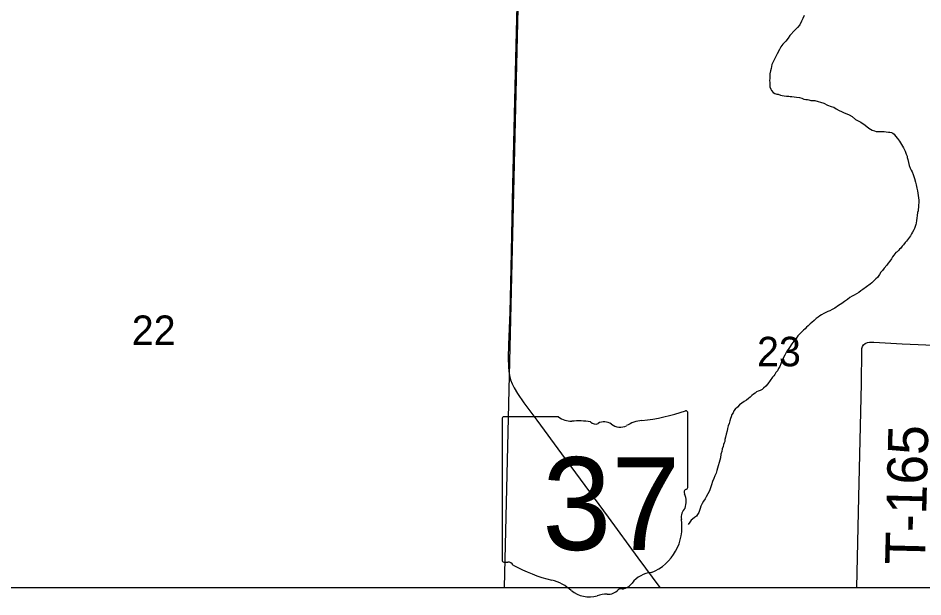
# Model space of a CAD drawing. Extents: x 0 to 68, y 0 to 52.9.
# Drawn here: x 47.275 to 48.632, y 31.129 to 31.998 of the extents above; entities that cross this region are included whole.
import ezdxf

# ---------------------------------------------------------------- set-up
doc = ezdxf.new("R2010")
doc.units = 0
for name, color, linetype in [('Default', 7, 'Continuous'), ('GM_X_Minor_River', 7, 'Continuous'), ('GM_X_State_Route', 7, 'Continuous'), ('GM_X_State_Shield', 7, 'Continuous'), ('GM_X_Township_Road', 7, 'Continuous'), ('GM_X_Township_Road_Text', 7, 'Continuous')]:
    doc.layers.add(name, color=color, linetype=linetype)

msp = doc.modelspace()

# ---------------------------------------------------------------- linework, layer by layer
at = {"layer": 'Default'}
msp.add_line((42.2581, 31.1431), (49.6501, 31.1431), dxfattribs=at)
msp.add_lwpolyline([(46.938, 31.1431), (46.9572, 32.0794), (48.0259, 32.0553), (48.0041, 31.1431)], dxfattribs=at)
at = {"layer": 'GM_X_Minor_River'}
for points in [[(48.4542, 32.0018), (48.4522, 31.9974), (48.4502, 31.9934), (48.4478, 31.9878), (48.4441, 31.9838), (48.4421, 31.9818), (48.4405, 31.9798), (48.4329, 31.9718), (48.4301, 31.9678), (48.4268, 31.9634), (48.4224, 31.9586), (48.4192, 31.9546), (48.4172, 31.9509), (48.414, 31.9441), (48.4115, 31.9393), (48.4095, 31.9353), (48.4075, 31.9313), (48.4059, 31.9281), (48.4051, 31.9253), (48.4047, 31.9221), (48.4039, 31.9185), (48.403, 31.9141), (48.4026, 31.9105), (48.4026, 31.9073), (48.4022, 31.904), (48.4026, 31.9012), (48.4026, 31.8988), (48.403, 31.8944), (48.4042, 31.8912), (48.4054, 31.8892), (48.4078, 31.886), (48.4102, 31.8844), (48.4134, 31.8835), (48.4154, 31.8835), (48.419, 31.8823), (48.4214, 31.8815), (48.4242, 31.8811), (48.4278, 31.8807), (48.4311, 31.8807), (48.4335, 31.8803), (48.4359, 31.8799), (48.4391, 31.8794), (48.4427, 31.879), (48.4471, 31.8786), (48.4507, 31.8774), (48.4539, 31.8762), (48.4567, 31.8758), (48.4591, 31.8754), (48.4611, 31.875), (48.4644, 31.8741), (48.4676, 31.8741), (48.4704, 31.8741), (48.4836, 31.8701), (48.4892, 31.8672), (48.4948, 31.8652), (48.4988, 31.864), (48.5025, 31.8616), (48.5069, 31.8592), (48.5105, 31.8575), (48.5141, 31.8555), (48.5181, 31.8543), (48.5217, 31.8527), (48.5261, 31.8499)], [(48.5261, 31.8499), (48.5313, 31.8458), (48.5393, 31.8414), (48.5457, 31.837), (48.5514, 31.8325), (48.5562, 31.8297), (48.5598, 31.8285), (48.5622, 31.8277), (48.5646, 31.8277), (48.5678, 31.8277), (48.571, 31.8277), (48.5742, 31.8276), (48.5774, 31.8272), (48.5806, 31.8268), (48.583, 31.8264), (48.5851, 31.826), (48.5871, 31.8252), (48.5891, 31.8236), (48.5915, 31.8208), (48.5943, 31.8171), (48.5975, 31.8131), (48.6003, 31.8083), (48.6031, 31.8031), (48.6059, 31.7982), (48.6074, 31.7934), (48.6086, 31.7906), (48.609, 31.7886), (48.6098, 31.7854), (48.6106, 31.781), (48.6118, 31.7766), (48.6134, 31.7725), (48.615, 31.7697), (48.6162, 31.7669), (48.6178, 31.7633), (48.6186, 31.7601), (48.6198, 31.7569), (48.6214, 31.7516), (48.6222, 31.7476), (48.6234, 31.7424), (48.6242, 31.7384), (48.6265, 31.7247), (48.6265, 31.7203), (48.6261, 31.7175), (48.6257, 31.7139), (48.6253, 31.7107), (48.6253, 31.7083), (48.6245, 31.7059), (48.6237, 31.7015), (48.6233, 31.6975), (48.6229, 31.6938), (48.6225, 31.6902), (48.6216, 31.6878), (48.6208, 31.685), (48.6196, 31.6822), (48.6188, 31.6798), (48.6168, 31.6766), (48.6152, 31.6738), (48.6136, 31.671), (48.6124, 31.669), (48.6108, 31.667), (48.6095, 31.665), (48.6079, 31.663), (48.6059, 31.661), (48.6031, 31.6574), (48.6011, 31.6554), (48.5995, 31.6526), (48.5971, 31.651), (48.5959, 31.649), (48.5938, 31.647), (48.5918, 31.6458), (48.589, 31.6418), (48.587, 31.6394), (48.5854, 31.6366), (48.583, 31.633), (48.5802, 31.6298), (48.5781, 31.627), (48.5745, 31.6222), (48.5717, 31.619), (48.5693, 31.6162), (48.5673, 31.613), (48.5645, 31.6086), (48.562, 31.6062), (48.56, 31.6042), (48.558, 31.6022), (48.5556, 31.6006), (48.5532, 31.5986), (48.5423, 31.5902), (48.5395, 31.5882), (48.5363, 31.5858), (48.5327, 31.5838), (48.5295, 31.5818), (48.5263, 31.5802), (48.523, 31.5782), (48.5194, 31.5754), (48.515, 31.5726), (48.5106, 31.5694), (48.5058, 31.5662), (48.5001, 31.5626), (48.4961, 31.5602), (48.4929, 31.5586), (48.4897, 31.5574)], [(48.4897, 31.5574), (48.4869, 31.5558), (48.4837, 31.5542), (48.4804, 31.5522), (48.478, 31.5507), (48.4752, 31.5491), (48.4724, 31.5467), (48.4692, 31.5439), (48.466, 31.5407), (48.4631, 31.5387), (48.4603, 31.5359), (48.4579, 31.5339), (48.4559, 31.5315), (48.4531, 31.5295), (48.4511, 31.5275), (48.4483, 31.5243), (48.445, 31.5211), (48.4422, 31.5171), (48.439, 31.5127), (48.4358, 31.5087), (48.4322, 31.5034), (48.4301, 31.5002), (48.4285, 31.4978), (48.4269, 31.495), (48.4253, 31.4918), (48.4233, 31.4882), (48.4217, 31.485), (48.4205, 31.4818), (48.4192, 31.4786), (48.4176, 31.475), (48.416, 31.4718), (48.4144, 31.4682), (48.4116, 31.4658), (48.4104, 31.463), (48.4088, 31.4606), (48.4068, 31.4586), (48.3999, 31.449), (48.3967, 31.4454), (48.3935, 31.4422), (48.3911, 31.4402), (48.3882, 31.4386), (48.3854, 31.4378), (48.383, 31.4366), (48.3806, 31.435), (48.3782, 31.4334), (48.3758, 31.4314), (48.3734, 31.429), (48.371, 31.4266), (48.3677, 31.4242), (48.3641, 31.4222), (48.3609, 31.4198), (48.3573, 31.4174), (48.3545, 31.4138), (48.3509, 31.411), (48.3488, 31.4082), (48.3476, 31.4054), (48.346, 31.4026), (48.3448, 31.3994), (48.3436, 31.3966), (48.3428, 31.3934), (48.3416, 31.3894), (48.3404, 31.3858), (48.3395, 31.3818), (48.3387, 31.3781), (48.3375, 31.3733), (48.3363, 31.3689), (48.3355, 31.3653), (48.3351, 31.3625), (48.3343, 31.3601), (48.3335, 31.3577), (48.3327, 31.3549), (48.3314, 31.3513), (48.3306, 31.3473), (48.3294, 31.3433), (48.3286, 31.3376), (48.327, 31.3308), (48.3254, 31.3256), (48.3241, 31.322), (48.3233, 31.3188), (48.3221, 31.3148), (48.3205, 31.3108), (48.3189, 31.3068), (48.3169, 31.302), (48.3153, 31.2972), (48.314, 31.2927), (48.3124, 31.2883), (48.3072, 31.2791), (48.3056, 31.2763), (48.3032, 31.2727), (48.3011, 31.2691), (48.2995, 31.2651), (48.2983, 31.2619), (48.2971, 31.2587), (48.2963, 31.2559), (48.2943, 31.2527), (48.2927, 31.2503), (48.2899, 31.2483), (48.287, 31.2459), (48.285, 31.2443), (48.2826, 31.2411), (48.2802, 31.2375)]]:
    msp.add_lwpolyline(points, dxfattribs=at)
at = {"layer": 'GM_X_State_Route'}
msp.add_lwpolyline([(48.0241, 32.0567), (48.0214, 31.9373), (48.0168, 31.7469), (48.0141, 31.6222), (48.0126, 31.5566), (48.0109, 31.5074), (48.0104, 31.4877), (48.0106, 31.4744), (48.0111, 31.4678), (48.0122, 31.4613), (48.0139, 31.4548), (48.0164, 31.4487), (48.0193, 31.4427), (48.0243, 31.4342), (48.0336, 31.4205), (48.0531, 31.3941), (48.0901, 31.3439), (48.1602, 31.2487), (48.2047, 31.1878), (48.238, 31.1431)], dxfattribs=at)
at = {"layer": 'GM_X_State_Shield'}
for p, q in [((48.0856, 31.3995), (48.0041, 31.3995)), ((48.2798, 31.2942), (48.2798, 31.4047)), ((48.0013, 31.3959), (48.0013, 31.1845)), ((48.2797, 31.2942), (48.2798, 31.2942))]:
    msp.add_line(p, q, dxfattribs=at)
for centre, radius, start, end in [((48.0045, 31.3963), 0.00323, 98.1301, 188.1301), ((48.105, 31.424), 0.0313, 231.6195, 271.1119), ((48.1806, 31.6876), 0.2953, 275.8445, 288.9065), ((48.2767, 31.4052), 0.0031, 351.8621, 97.738), ((48.1154, 31.2809), 0.1123, 80.4867, 94.9883), ((48.1409, 31.3974), 0.00903, 219.7921, 297.1024), ((48.1542, 31.373), 0.0188, 54.4667, 119.1411), ((48.1784, 31.4065), 0.0226, 233.8562, 294.8282), ((48.2182, 31.335), 0.0594, 97.3462, 120.7689), ((48.2765, 31.2938), 0.00332, 289.6038, 7.7341), ((48.279, 31.2861), 0.0048, 107.944, 210.337), ((48.2485, 31.2721), 0.0288, 340.033, 23.6496), ((48.2909, 31.2479), 0.021, 136.8065, 186.9296), ((48.1971, 31.2339), 0.0739, 292.3089, 8.9858), ((48.0046, 31.1841), 0.00325, 171.9584, 258.3066), ((48.005, 31.2057), 0.0248, 267.339, 280.6039), ((48.0101, 31.1724), 0.00895, 29.7484, 93.2717), ((48.1232, 31.3622), 0.2132, 240.4129, 257.1985), ((48.2283, 31.1252), 0.0404, 94.4031, 142.5768), ((48.0596, 31.0896), 0.0667, 47.1842, 75.836), ((48.177, 31.1641), 0.0239, 282.8732, 323.2771), ((48.1318, 31.1713), 0.0423, 230.7004, 286.2918), ((48.1562, 31.0982), 0.0348, 85.6951, 111.2099), ((48.1593, 31.1555), 0.0226, 268.777, 315.5493), ((48.1797, 31.135), 0.00635, 65.7517, 132.6484)]:
    msp.add_arc(centre, radius, start, end, dxfattribs=at)
at = {"layer": 'GM_X_Township_Road'}
msp.add_lwpolyline([(48.5332, 31.1431), (48.5365, 31.2785), (48.5403, 31.4492), (48.5406, 31.4986), (48.5408, 31.5019), (48.5417, 31.505), (48.5435, 31.5076), (48.546, 31.5096), (48.5491, 31.5108), (48.5523, 31.5114), (48.5589, 31.5112), (48.6015, 31.5087), (48.7557, 31.5025), (48.782, 31.5016), (48.7951, 31.5024), (48.8146, 31.5048), (48.8277, 31.5053), (48.8639, 31.5041), (48.9951, 31.4977), (49.0593, 31.4943)], dxfattribs=at)

# ---------------------------------------------------------------- texts
at = {"layer": 'Default'}
for s, p in [('22', (47.4455, 31.5072)), ('23', (48.3836, 31.4752))]:
    msp.add_text(s, height=0.0442, rotation=0, dxfattribs=at).set_placement(p)
at = {"layer": 'GM_X_State_Shield'}
msp.add_text('37', height=0.13922, dxfattribs=at).set_placement((48.0614, 31.1995))
at = {"layer": 'GM_X_Township_Road_Text'}
msp.add_text('T-165', height=0.06, rotation=88.5957, dxfattribs=at).set_placement((48.6356, 31.1767))

doc.saveas('drawing.dxf')
